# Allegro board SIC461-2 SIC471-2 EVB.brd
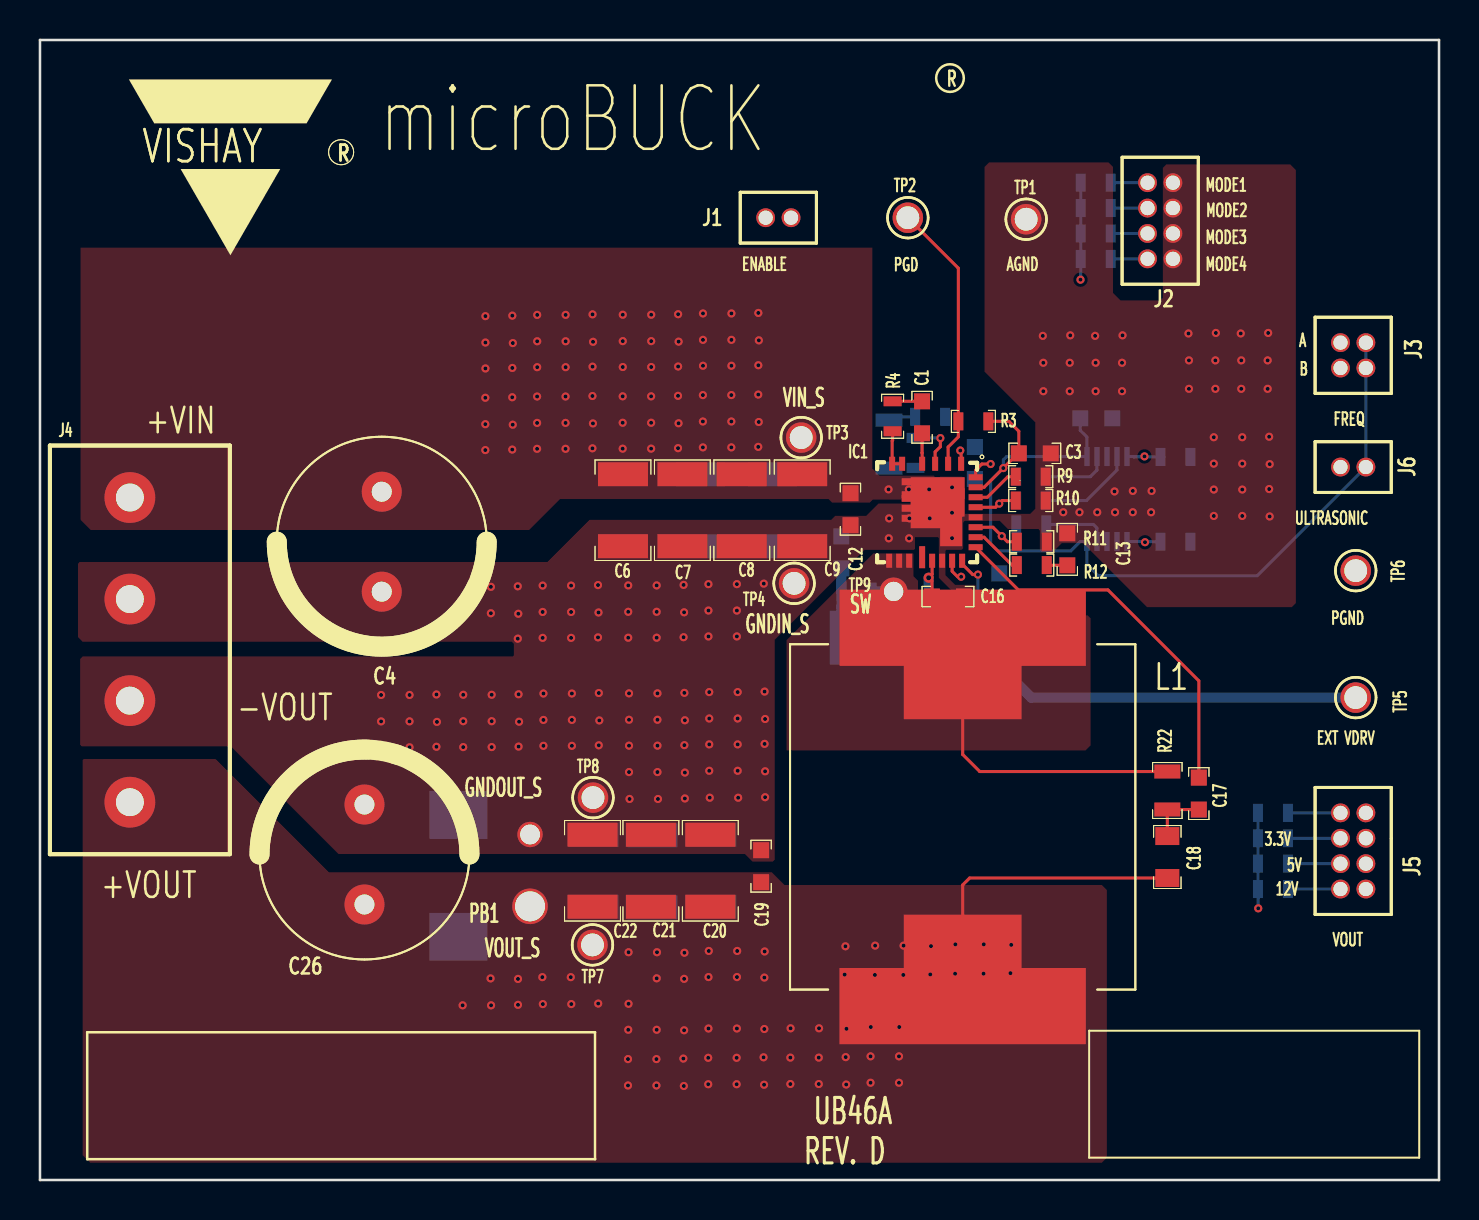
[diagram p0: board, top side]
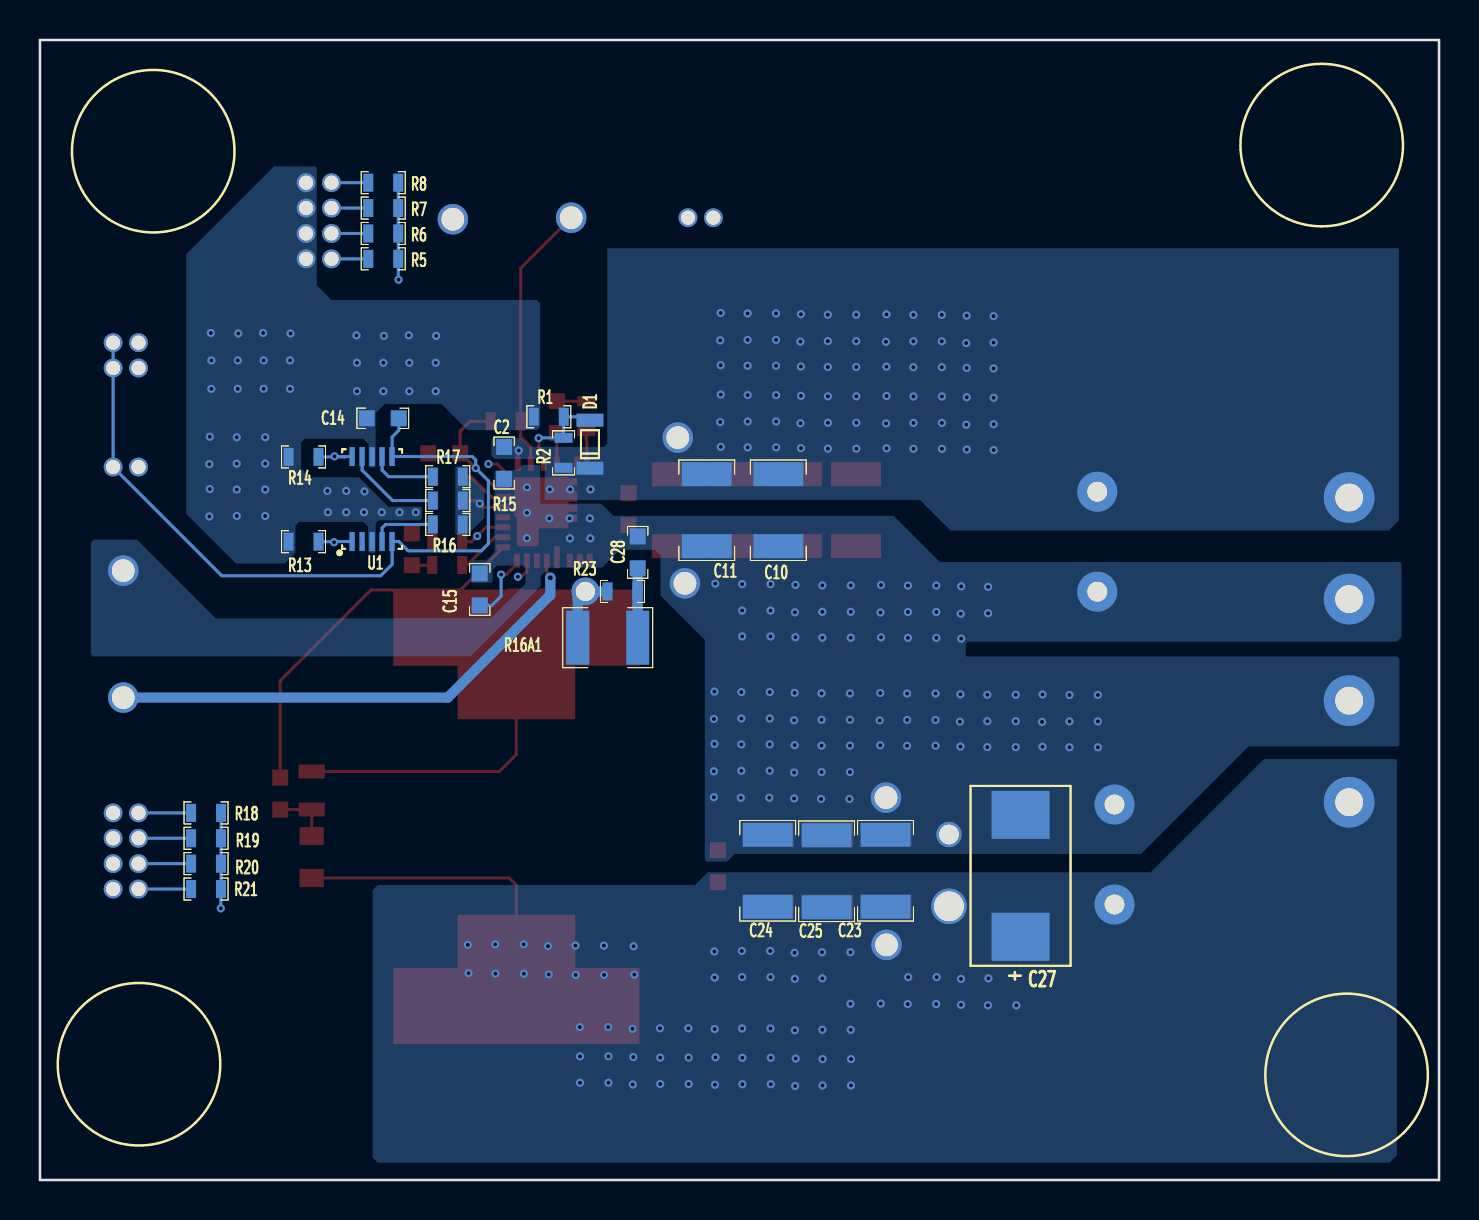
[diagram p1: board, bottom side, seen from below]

Outline 69.98 x 57.02 mm; copper layers: TOP, LAYER2, LAYER3, LAYER4, LAYER5, BOTTOM. Coordinates in mm from the lower left corner of the outline.
Outline path: 49.02,35 49.02,35 ; 0,57.02 0,0 69.98,0 69.98,57.02 0,57.02

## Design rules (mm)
constraint set DEFAULT: min track width 0.1

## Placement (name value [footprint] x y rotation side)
C1  100n  [C0603-TDK]  44.12 38.15 270 top
C2  0.1uF  [C0603-TDK]  46.76 35.86 270 bottom
C3  1u  [C0603-TDK]  49.76 36.35 0 top
C4  100uF 63V  [CAP10P5]  17.09 31.93 270 top
C6  2.2uF  [C1210-TDK]  29.16 33.5 90 top
C7  2.2uF  [C1210-TDK]  32.13 33.5 90 top
C8  2.2uF  [C1210-TDK]  35.1 33.5 90 top
C9  2.2uF  [C1210-TDK]  38.13 33.5 90 top
C10  2.2uF  [C1210-TDK]  33.05 33.5 90 bottom
C11  2.2uF  [C1210-TDK]  36.63 33.5 90 bottom
C12  0.1uF  [C0603-TDK]  40.54 33.55 270 top
C13  1n  [C0603-TDK]  51.38 31.55 90 top
C14  1uF  [C0603-TDK]  52.83 38.1 180 bottom
C15  33nF  [C0603-TDK]  47.98 29.54 270 bottom
C16  4.7uF  [C0603-TDK]  45.42 29.18 0 top
C17  2.2nF  [C0603-TDK]  57.96 19.33 270 top
C18  560p  [C0805-TDK]  56.39 16.15 270 top
C19  0.1uF  [C0603-TDK]  36.07 15.7 270 top
C20  22uF  [C1210-TDK]  33.53 15.47 270 top
C21  22uF  [C1210-TDK]  30.56 15.47 270 top
C22  22uF  [C1210-TDK]  27.64 15.47 270 top
C23  22uF  [C1210-TDK]  27.69 15.47 270 bottom
C24  22uF  [C1210-TDK]  33.58 15.47 270 bottom
C25  22uF  [C1210-TDK]  30.63 15.44 270 bottom
C26  DNP  [CAP10P5]  16.23 16.28 90 top
C27  100uF 20V  [D3L]  20.93 15.21 90 bottom
C28  DNP  [C0603-TDK]  40.08 31.39 90 bottom
D1  8.2V  [SOD323]  42.47 36.8 90 bottom
IC1  SiC46X  [SIC471]  44.37 33.4 270 top
J1  HEADER2x1  [MINIJUMPER2]  36.3 48.13 0 top
J2  HEADER 4X2  [MINIJUMPER2X4]  56.67 46.08 180 top
J3  HEADER 2X2  [MINIJUMPER2X2]  66.32 41.88 270 top
J4  CON4  [ED120-4DS2]  4.5 34.14 270 top
J5  HEADER 4X2  [MINIJUMPER2X4]  65.05 18.36 0 top
J6  JUMPER  [MINIJUMPER2]  65.05 35.66 0 top
L1  15uH  [IHLP50506767]  46.15 18.16 270 top
NOREF  -  []  9.52 46.25 0 top
PB1  CON2  [2PROBE]  24.51 13.69 135 top
R1  10K  [R0603-VISHAY]  44.53 38.18 180 bottom
R2  DNP  [R0603-VISHAY]  43.79 36.37 90 bottom
R3  102K  [R0603-VISHAY]  46.69 37.95 180 top
R4  3.3  [R0603-VISHAY]  42.65 38.2 270 top
R5  2K  [R0603-VISHAY]  52.81 46.08 0 bottom
R6  301K  [R0603-VISHAY]  52.81 47.35 0 bottom
R7  499K  [R0603-VISHAY]  52.81 48.62 0 bottom
R8  1M  [R0603-VISHAY]  52.81 49.89 0 bottom
R9  47k  [R0603-VISHAY]  49.56 35.18 180 top
R10  DNP  [R0603-VISHAY]  49.56 33.99 180 top
R11  10K  [R0603-VISHAY]  49.61 31.93 180 top
R12  56k  [R0603-VISHAY]  49.61 30.76 180 top
R13  100k  [R0603-VISHAY]  56.79 31.93 180 bottom
R14  100k  [R0603-VISHAY]  56.79 36.17 0 bottom
R15  43.2K  [R0603-VISHAY]  49.58 33.99 180 bottom
R16  64.9K  [R0603-VISHAY]  49.58 32.79 0 bottom
R16A1  DNP  [1210]  41.58 27.13 180 bottom
R17  43.2K  [R0603-VISHAY]  49.58 35.18 180 bottom
R18  DNP  [R0603-VISHAY]  61.67 18.36 180 bottom
R19  31.6K  [R0603-VISHAY]  61.67 17.09 180 bottom
R20  52.3K  [R0603-VISHAY]  61.67 15.82 180 bottom
R21  52.3K  [R0603-VISHAY]  61.67 14.55 180 bottom
R22  49.9K  [R0805-VISHAY]  56.39 19.48 90 top
R23  DNP  [R0603-VISHAY]  40.84 29.44 180 bottom
TP1  CON1  [TP30]  49.33 48.06 0 top
TP2  CON1  [TP30]  43.41 48.13 0 top
TP3  CON1  [TP30]  38.07 37.13 0 top
TP4  CON1  [TP30]  37.72 29.84 0 top
TP5  CON1  [TP30]  65.81 24.13 0 top
TP6  CON1  [TP30]  65.81 30.48 0 top
TP7  CON1  [TP30]  27.64 11.76 0 top
TP8  CON1  [TP30]  27.66 19.13 0 top
TP9  5002  [TP]  42.7 29.44 0 top
U1  DG2034  [MSOP10]  53.37 34.06 180 bottom

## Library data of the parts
C1 C3 = CAPACITOR NON-POL
C2 C6-C25 C28 = CAP NP
C4 C26 C27 = CAP POL
D1 = DIODE ZENER
IC1 = SiC462W
J1 = CON2: User Part Number: ***
J2 J5 = HEADER 4X2
J3 = HEADER 2X2
J4 = HEADER 4
J6 = JUMPER: User Part Number: ***
L1 = INDUCTOR
PB1 = CON2
R1-R3 R5-R16 R16A1 R17-R23 = RESISTOR
R4 = R
TP1-TP8 = CON1
TP9 = TP_0
U1 = DG2034M

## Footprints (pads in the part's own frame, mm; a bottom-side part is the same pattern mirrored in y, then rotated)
2PROBE
  round 1.778 hole 1.499: 1(0,0)
  round 1.27 hole 0.991: 2(2.54,-2.54)
1210
  rect 1.15x2.7 smd: 1(-1.5,0) 2(1.5,0)
C0603-TDK
  rect 0.8x0.8 smd: 1(-0.8,0) 2(0.8,0)
C0805-TDK
  rect 0.9x1.2 smd: 1(-1.05,0) 2(1.05,0)
C1210-TDK
  rect 1.2x2.5 smd: 1(-1.8,0) 2(1.8,0)
CAP10P5
  round 2 hole 1: 1(-2.5,0) 2(2.5,0)
D3L
  rect 2.4x2.9 smd: 1(-3.05,0) 2(3.05,0)
ED120-4DS2
  round 2.54 hole 1.397: 1(0,0) 2(5.08,0) 3(10.16,0) 4(15.24,0)
IHLP50506767
  custom 1.619x1.619 smd: 1(-8.128,0) 2(8.128,0)
MINIJUMPER2
  round 0.94 hole 0.711: 1(0,0) 2(1.27,0)
MINIJUMPER2X2
  round 0.94 hole 0.711: 1(0,0) 2(1.27,0) 3(0,-1.27) 4(1.27,-1.27)
MINIJUMPER2X4
  round 0.94 hole 0.711: 1(0,0) 2(1.27,0) 3(0,-1.27) 4(1.27,-1.27) 5(0,-2.54) 6(1.27,-2.54) 7(0,-3.81) 8(1.27,-3.81)
MSOP10
  rect 0.27x0.95 smd: 1(-1,-2.125) 2(-0.5,-2.125) 3(0,-2.125) 4(0.5,-2.125) 5(1,-2.125) 6(1,2.125) 7(0.5,2.125) 8(0,2.125) 9(-0.5,2.125) 10(-1,2.125)
R0603-VISHAY
  rect 0.5x0.9 smd: 1(-0.75,0) 2(0.75,0)
R0805-VISHAY
  rect 0.7x1.3 smd: 1(-0.95,0) 2(0.95,0)
SIC471
  rect 0.7x0.3 smd: 1(-2.425,1.7) 2(-2.425,1.05) 3(-2.425,0.4) 4(-2.425,-0.25) 5(-2.425,-1.25) 6(-2.425,-1.75) 12(2.425,-1.9) 13(2.425,-1.4) 14(2.425,-0.9) 16(2.425,0.25) 17(2.425,0.75) 18(2.425,1.25) 19(2.425,1.75)
  custom 0.275x0.275 smd: 7(-1.2,0.3)
  round 0 smd: 8(-0.914,-2.54) 10(0.66,-2.565) 11(1.168,-2.515)
  custom 0.5x0.5 smd: 9(-0.2,0.3)
  rect 1.1x0.3 smd: 15(2.25,-0.25)
  rect 0.3x0.7 smd: 20(1.75,2.425) 21(1.25,2.425) 22(0.75,2.425) 23(0.25,2.425) 24(-0.25,2.425) 25(-0.75,2.425) 26(-1.25,2.425) 27(-1.75,2.425)
  rect 3.4x1.1 smd: 28(0,1.2)
SOD323
  rect 0.65x1.35 smd: 1(-1.2,0) 2(1.2,0)
TP
  round 1.397 hole 0.965: 1(0,0)
TP30
  round 1.524 hole 1.143: 1(0,0)

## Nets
GND: C2.2 C3.2 C4.2 C6.1 C7.1 C8.1 C9.1 C10.1 C11.1 C12.2 C13.2 C14.1 C15.1 C16.2 C19.1 C20.1 C21.1 C22.1 C23.1 C24.1 C25.1 C26.2 C27.2 C28.2 IC1.9 IC1.10 IC1.11 IC1.17 IC1.23 IC1.28 J1.2 J2.1 J2.3 J2.5 J2.7 J4.2 J4.3 PB1.2 R1.1 R9.1 R10.1 R11.1 R13.1 R14.2 TP1.1 TP4.1 TP6.1 TP8.1 U1.3 U1.8
VDD1: C3.1 C14.2 IC1.26 J3.1 J3.2(4) J6.2 R3.1 U1.5 U1.6(V+)
VIN: C2.1 C4.1 C6.2 C7.2 C8.2 C9.2 C10.2 C11.2 C12.1 D1.1(CATHODE) IC1.1 IC1.7 IC1.8 J4.1 R2.1 TP3.1
COMP: IC1.21 R12.2
EN: D1.2 IC1.3 J1.1 R1.2 R2.2
FSW: IC1.24 R10.2 R15.2 R16.1 R17.2
GL: IC1.15
ILIM: IC1.25 R9.2
PGD: IC1.2 R3.2 TP2.1
VO: C18.2 C19.2 C20.2 C21.2 C22.2 C23.2 C24.2 C25.2 C26.1 C27.1 J4.4 L1.2 PB1.1 R18.2 R19.2 R20.2 R21.2 TP7.1
N9136645: IC1.12 IC1.13 IC1.14 L1.1 R16A1.1 R22.2 R23.1 TP9.1
N9138289: IC1.22 J5.2 J5.4 J5.6 J5.8 R11.2
N9138679: C13.1 R12.1
N9140488: C1.1 R4.1
N9140516: C1.2 IC1.4
N9145499: C16.1 IC1.16 TP5.1
N10371426: IC1.5 IC1.6 R4.2
N10441290: IC1.18 J6.1
N10450769: C17.1 IC1.20(VSNS)
N10621393: C17.2 C18.1 R22.1
N10653497: IC1.27 R5.1 R6.1 R7.1 R8.1
N10653505: J2.2 R5.2
N10653567: J2.4 R6.2
N10653613: J2.6 R7.2
N10653671: J2.8 R8.2
N16777491: J5.1 R18.1
N16777524: J5.3 R19.1
N16777532: J5.5 R20.1
N16777536: J5.7 R21.1
N16796780: C28.1 R16A1.2 R23.2
N16799725: J3.3 R13.2 U1.1
N16799736: J3.4 R14.1 U1.10
N16799803: R15.1 U1.9
N16799837: R16.2 U1.4
N16799839: R17.1 U1.7
N1041946515: C15.2 IC1.19

Pads without a net: U1 2

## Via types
v1: diameter 0.406, hole 0.203, TOP to BOTTOM, 290 vias
v2: diameter 0.508, hole 0.254, TOP to BOTTOM, 1 via

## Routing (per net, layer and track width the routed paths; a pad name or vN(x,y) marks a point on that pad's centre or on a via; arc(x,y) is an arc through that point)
GND:
  vias: v1(17.06,24.26) v1(17.06,22.94) v1(17.06,21.64) v1(18.48,24.26) v1(18.48,22.94) v1(18.48,21.64) v1(19.83,24.29) v1(19.86,22.91) v1(19.83,21.67) v1(21.17,24.27) v1(21.17,22.95) v1(21.17,21.65) v1(22.55,29.67) v1(22.55,28.35) v1(22.59,24.27) v1(22.59,22.95) v1(22.59,21.65) v1(23.9,29.7) v1(23.92,28.32) v1(23.9,27.08) v1(23.94,24.3) v1(23.96,22.92) v1(23.94,21.68) v1(25.14,29.73) v1(25.14,28.41) v1(25.14,27.12) v1(25.18,24.33) v1(25.18,23.01) v1(25.18,21.72) v1(26.57,29.73) v1(26.57,28.41) v1(26.57,27.12) v1(26.6,24.33) v1(26.6,23.01) v1(26.6,21.72) v1(27.91,29.76) v1(27.94,28.39) v1(27.91,27.14) v1(27.95,24.36) v1(27.95,21.74) v1(27.98,22.99) v1(29.42,29.74) v1(29.42,28.42) v1(29.42,27.13) v1(29.46,24.34) v1(29.46,23.02) v1(29.46,21.73) v1(29.46,20.41) v1(29.49,19.06) v1(30.85,29.74) v1(30.85,28.42) v1(30.85,27.13) v1(30.88,24.34) v1(30.88,23.02) v1(30.88,21.73) v1(30.88,20.41) v1(30.91,19.06) v1(32.19,29.77) v1(32.22,28.4) v1(32.19,27.15) v1(32.23,24.37) v1(32.26,23) v1(32.23,21.75) v1(32.26,20.38) v1(32.26,19.08) v1(33.44,29.81) v1(33.44,28.48) v1(33.44,27.19) v1(33.47,24.41) v1(33.47,23.08) v1(33.47,21.79) v1(33.47,20.47) v1(33.5,19.12) v1(34.86,29.81) v1(34.86,28.48) v1(34.86,27.19) v1(34.9,24.41) v1(34.9,23.08) v1(34.9,21.79) v1(34.9,20.47) v1(34.92,19.12) v1(36.2,29.83) v1(36.24,24.43) v1(36.27,23.06) v1(36.24,21.81) v1(36.27,20.44) v1(36.27,19.15) v1(42.47,33.1) v1(42.45,32.1) v1(43.47,32.1) v1(43.49,33.1) v1(44.5,33.1) v1(45.62,34.65) v1(45.62,33.38) v1(45.62,32.11) v1(50.16,42.22) v1(50.18,40.88) v1(50.18,39.46) v1(51.18,33.4) v1(51.53,42.25) v1(51.51,40.88) v1(51.51,39.46) v1(51.99,33.4) v1(52.78,42.22) v1(52.8,40.88) v1(52.8,39.46) v1(52.88,33.4) v1(53.75,34.44) v1(53.77,33.4) v1(54.15,42.25) v1(54.12,40.88) v1(54.12,39.46) v1(54.66,34.47) v1(54.66,33.4) v1(55.58,33.4) v1(55.6,34.47) v1(57.44,42.34) v1(57.47,41) v1(57.47,39.57) v1(58.71,37.15) v1(58.71,35.83) v1(58.71,34.54) v1(58.71,33.22) v1(58.82,42.37) v1(58.79,41) v1(58.79,39.57) v1(60.06,42.34) v1(60.09,41) v1(60.09,39.57) v1(60.13,37.15) v1(60.13,35.83) v1(60.13,34.54) v1(60.13,33.22) v1(61.43,42.37) v1(61.41,41) v1(61.41,39.57) v1(61.48,37.18) v1(61.51,35.81) v1(61.48,34.56) v1(61.51,33.19)
VDD1: length 45.4
  TOP w0.152: IC1.26 47.22,34.65 v1(48.18,35.61) 48.92,36.35 C3.1 48.96,37.45 48.46,37.95 R3.1
  BOTTOM w0.152: C14.2 52.03,37.5 52.37,37.16 U1.6 48.35,36.19 48.18,36.02 v1(48.18,35.61) 47.55,34.98 47.55,31.83 47.9,31.47 51.56,31.47 52.03,31.94 U1.5 52.37,30.79 52.93,30.23 60.88,30.23 J6.2 J3.2 J3.1
VIN: length 0.7
  TOP w0.152: v1(46.03,36.49) 46.07,36.45 IC1.1
  vias: v1(22.27,39.13) v1(22.27,37.81) v1(22.27,36.51) v1(22.28,43.21) v1(22.28,41.89) v1(22.28,40.59) v1(23.63,43.24) v1(23.65,41.86) v1(23.63,40.62) v1(23.62,39.15) v1(23.65,37.78) v1(23.62,36.54) v1(24.87,43.27) v1(24.87,41.95) v1(24.87,40.66) v1(24.86,39.19) v1(24.86,37.87) v1(24.86,36.57) v1(26.29,43.27) v1(26.29,41.95) v1(26.29,40.66) v1(26.29,39.19) v1(26.29,37.87) v1(26.29,36.57) v1(27.64,43.3) v1(27.66,41.93) v1(27.64,40.68) v1(27.63,39.22) v1(27.66,37.84) v1(27.63,36.6) v1(29.15,43.28) v1(29.15,41.96) v1(29.15,40.67) v1(29.14,39.2) v1(29.14,37.88) v1(29.14,36.58) v1(30.57,43.28) v1(30.57,41.96) v1(30.57,40.67) v1(30.57,39.2) v1(30.57,37.88) v1(30.57,36.58) v1(31.92,43.31) v1(31.94,41.94) v1(31.92,40.69) v1(31.91,39.22) v1(31.94,37.85) v1(31.91,36.61) v1(33.16,43.34) v1(33.16,42.02) v1(33.16,40.73) v1(33.16,39.26) v1(33.16,37.94) v1(33.16,36.65) v1(34.58,43.34) v1(34.58,42.02) v1(34.58,40.73) v1(34.58,39.26) v1(34.58,37.94) v1(34.58,36.65) v1(35.93,43.37) v1(35.96,42) v1(35.93,40.75) v1(35.93,39.29) v1(35.95,37.92) v1(35.93,36.67) v1(42.44,34.54) v1(43.46,34.54) v1(44.48,34.54)
COMP: length 2.6
  TOP w0.152: R12.2 48.62,30.76 47.22,32.15 IC1.21
EN: length 25.4
  TOP w0.152: IC1.3 44.77,36.42 45.03,36.68 v1(45.03,37.11)
  LAYER3 w0.152: J1.1 36.3,49.3 36.6,49.6 41.23,49.6 42.06,48.77 42.06,40.08 v1(45.03,37.11)
  BOTTOM w0.152: v1(45.03,37.11) 45.03,37.12 R2.2 43.79,38.16 R1.2 42.64,38.18 D1.2
FSW: length 2.2
  TOP w0.152: IC1.24 47.8,33.65 v1(47.98,33.83) 48.13,33.99 R10.2
  BOTTOM w0.152: 48.83,32.74 R16.1
ILIM: length 2.4
  TOP w0.152: IC1.25 47.38,34.15 48.41,35.18 R9.2
PGD: length 13.6
  TOP w0.152: TP2.1 45.94,45.61 R3.2 45.94,37.17 45.42,36.66 IC1.2
VO: length 56.8
  TOP w0.152: 46.15,10.03 46.15,14.76 46.5,15.1 C18.2
  LAYER3 w0.152: TP7.1 31.09,8.31 55.65,8.31 v1(60.93,13.59)
  BOTTOM w0.152: R18.2 R19.2 R20.2 R21.2 60.93,14.54 v1(60.93,13.59)
  vias: v1(21.14,8.74) v1(22.54,10.08) v1(22.56,8.74) v1(23.91,10.06) v1(23.91,8.76) v1(25.13,10.15) v1(25.15,8.8) v1(26.55,10.15) v1(26.57,8.8) v1(27.92,8.83) v1(29.44,11.39) v1(29.44,8.81) v1(29.42,7.52) v1(29.41,6.05) v1(29.41,4.73) v1(30.86,11.39) v1(30.85,10.09) v1(30.85,7.52) v1(30.83,6.05) v1(30.83,4.73) v1(32.23,11.37) v1(32.22,10.06) v1(32.22,7.49) v1(32.18,6.07) v1(32.21,4.7) v1(33.45,11.46) v1(33.44,10.15) v1(33.44,7.58) v1(33.42,6.11) v1(33.42,4.79) v1(34.87,11.46) v1(34.86,10.15) v1(34.86,7.58) v1(34.85,6.11) v1(34.85,4.79) v1(36.25,11.43) v1(36.23,10.13) v1(36.23,7.55) v1(36.19,6.14) v1(36.22,4.77) v1(37.54,7.59) v1(37.53,6.12) v1(37.53,4.8) v1(38.97,7.59) v1(38.95,6.12) v1(38.95,4.8) v1(40.25,10.28) v1(40.29,11.69) v1(40.34,7.56) v1(40.3,6.15) v1(40.33,4.78) v1(41.56,7.65) v1(41.54,6.19) v1(41.54,4.86) v1(41.77,11.72) v1(41.76,10.26) v1(42.97,6.19) v1(42.97,4.86) v1(42.98,7.65) v1(43.2,11.72) v1(43.18,10.26) v1(44.57,11.7) v1(44.53,10.28) v1(45.77,10.32) v1(45.78,11.79) v1(47.21,11.79) v1(47.19,10.32) v1(48.54,10.35) v1(48.58,11.76)
N9136645: length 19.2
  TOP w0.152: L1.1 46.15,21.29 47.01,20.43 R22.2
  BOTTOM w0.508: R23.1 TP9.1 43.08,29.06 R16A1.1
N9138289: length 30.9
  TOP w0.152: IC1.22 47.66,32.65 v1(48.11,32.21) 48.39,31.93 R11.2
  LAYER3 w0.152: J5.8 J5.6 J5.4 J5.2 66.32,19.68 53.8,32.21 v1(48.11,32.21)
N9138679: length 1
  TOP w0.152: C13.1 50.37,30.75 R12.1
N9140488: length 1.5
  TOP w0.152: 42.66,38.95 R4.1 ; 42.66,38.95 C1.1 ; 42.66,38.95 42.65,38.94
N9140516: length 1.5
  TOP w0.152: IC1.4 44.12,36.38 44.12,36.38 C1.2
N9145499: length 26.3
  TOP w0.152: C16.1 44.62,29.96 v2(44.45,30.12) 44.62,30.3 IC1.16
  BOTTOM w0.508: v2(44.45,30.12) 44.45,29.26 49.58,24.13 TP5.1
N10371426: length 2.1
  TOP w0.152: R4.2 42.65,37 42.62,36.98 IC1.6 IC1.5
N10441290: length 24
  TOP w0.152: IC1.18 45.62,30.45 45.9,30.18 v1(46.08,30.18)
  LAYER3 w0.152: J6.1 65.05,33.83 63.88,32.66 47.57,32.66 46.08,31.17 v1(46.08,30.18)
N10450769: length 18.8
  TOP w0.152: C17.1 57.96,24.97 53.42,29.51 48.93,29.51 IC1.20
N10621393: length 2.9
  TOP w0.152: C18.1 R22.1 57.5,18.53 57.51,18.53 C17.2
N10653497: length 17.2
  TOP w0.152: IC1.27 46.8,35.5 47.11,35.81 v1(47.55,35.81)
  LAYER3 w0.152: v1(52.04,45.03) 47.55,40.54 v1(47.55,35.81) 47.52,35.79
  BOTTOM w0.152: R8.1 R7.1 R6.1 R5.1 52.06,45.05 v1(52.04,45.03)
N10653505: length 1.8
  BOTTOM w0.152: J2.2 R5.2
N10653567: length 1.8
  BOTTOM w0.152: J2.4 R6.2
N10653613: length 1.8
  BOTTOM w0.152: J2.6 R7.2
N10653671: length 1.8
  BOTTOM w0.152: J2.8 R8.2
N16777491: length 2.6
  BOTTOM w0.152: J5.1 R18.1
N16777524: length 2.6
  BOTTOM w0.152: J5.3 R19.1
N16777532: length 2.6
  BOTTOM w0.152: J5.5 R20.1
N16777536: length 2.6
  BOTTOM w0.152: J5.7 R21.1
N16796780: length 3.5
  BOTTOM w0.508: C28.1 40.08,29.45 R23.2 40.09,28.69 40.08,28.68 R16A1.2
N16799725: length 28.5
  LAYER3 w0.152: J3.3 65.05,42.8 65.35,43.1 67.79,43.1 68.07,42.82 68.07,33.96 66.01,31.9 v1(55.27,31.9)
  BOTTOM w0.152: U1.1 55.24,31.94 55.24,31.93 ; 55.24,31.93 55.22,31.9 ; 55.24,31.93 R13.2 ; 55.24,31.93 v1(55.27,31.9)
N16799736: length 14
  LAYER3 w0.152: J3.4 62.89,38.46 57.51,38.46 v1(55.24,36.2)
  BOTTOM w0.152: 54.7,36.19 55.24,36.19 v1(55.24,36.2) ; 54.7,36.19 U1.10 ; 54.7,36.19 54.72,36.17 R14.1 56.22,36.17
N16799803: length 4.8
  BOTTOM w0.152: R15.1 52.34,33.99 53.87,35.51 U1.9
N16799837: length 3.3
  BOTTOM w0.152: R16.2 52.69,32.79 52.87,32.61 U1.4
N16799839: length 3.3
  BOTTOM w0.152: R17.1 52.54,35.18 52.87,35.51 U1.7
N1041946515: length 3.5
  TOP w0.152: IC1.19 46.12,30.81 46.65,30.28 v1(46.91,30.28)
  BOTTOM w0.152: v1(46.91,30.28) 46.91,29.2 47.38,28.74 C15.2

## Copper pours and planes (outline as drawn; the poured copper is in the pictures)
GND on TOP: outline of 85 points within 1.91,15.93 62.81,50.9
GND on BOTTOM: 41.3,33.22 41.91,33.83 44.93,33.83 44.96,33.86 44.96,35.74 44.98,35.76 45.85,35.76 46.1,35.51 47.17,35.51 47.24,35.43 47.24,31.39 47.65,30.99 48.31,30.99 48.44,30.86 48.44,29.92 48.39,29.87 47.42,29.87 47.34,29.95 47.34,30.5 47.12,30.73 45.74,30.73 45.69,30.68 45.69,29.82 47.42,28.09 61.19,28.09 65.12,32.03 67.28,32.03 67.44,31.88 67.44,26.29 67.33,26.19 48.46,26.19 44.93,29.72 44.93,30.23 44.53,30.63 41.86,30.63 40.97,31.52 39.22,31.52 38.94,31.24 38.94,29.23 36.73,27.03 36.73,16.03 36.63,15.93 35.61,15.93 35.23,16.31 14.91,16.31 9.55,21.67 9.55,21.69 2.06,21.69 1.98,21.77 1.98,26.06 2.11,26.19 23.62,26.19 23.67,26.24 23.67,26.82 23.57,26.92 2.11,26.92 1.88,27.15 1.88,30.84 1.95,30.91 24.97,30.91 27.28,33.22
GND on BOTTOM: 53.49,31.37 53.57,31.45 53.57,32.69 53.8,32.92 57.02,32.92 57.2,32.74 57.2,31.37 57.73,30.84 60.17,30.84 62.66,33.32 62.66,46.3 58.27,50.7 56.18,50.7 56.13,50.65 56.13,44.75 55.4,44.02 45.14,44.02 44.96,43.84 44.96,37.67 45.11,37.52 48.59,37.52 49.89,38.81 52.73,38.81 53.19,38.35 53.19,35.69 53.24,35.64 53.49,35.64 53.54,35.69 53.54,36.8 53.82,37.08 56.72,37.08 56.92,36.88 56.92,35.61 56.46,35.15 54.03,35.15 52.55,33.68 50.93,33.68 50.88,33.63 50.88,33.1 50.98,32.99 53.06,32.99 53.19,32.87 53.19,31.42 53.24,31.37
GND on LAYER2: 1.06,55.87 1.06,0.8 55.47,0.8 55.52,0.86 55.52,27.17 55.44,27.25 46.35,27.25 45,28.59 45,35.3 44.49,35.81 42.59,35.81 33.29,45.1 33.29,55.8 33.22,55.87
GND on LAYER2: 69.03,0.93 69.03,55.87 33.8,55.87 33.7,55.77 33.7,45.03 42.54,36.19 44.62,36.19 45.26,35.55 45.26,28.82 46.68,27.4 55.44,27.4 55.7,27.14 55.7,0.88 55.77,0.8 68.9,0.8
GND on LAYER3: 44.98,35.13 45.03,35.18 48.06,35.18 48.72,35.84 48.72,38.96 47.24,40.44 47.24,50.67 47.47,50.9 53.44,50.9 53.67,50.67 53.67,44.37 54.05,43.99 56.03,43.99 56.16,44.12 56.16,50.62 56.34,50.8 62.53,50.8 62.81,50.52 62.81,33.55 62.79,33.55 62.13,32.89 46.96,32.89 45.59,31.52 42.27,31.52 41.4,30.66 41.4,28.68 43.23,26.85 58.22,26.85 59.51,25.55 59.51,16.43 59.39,16.31 14.94,16.31 9.58,21.67 9.58,21.69 2.08,21.69 2.01,21.77 2.01,26.06 2.13,26.19 23.65,26.19 23.7,26.24 23.7,26.82 23.6,26.92 2.13,26.92 1.91,27.15 1.91,31.42 1.96,31.47 24.41,31.47 26.62,33.68 44.91,33.68 44.98,33.76
GND on LAYER4: 1.07,55.88 1.07,0.81 55.47,0.81 55.52,0.86 55.52,27.18 55.45,27.25 46.35,27.25 45.01,28.6 45.01,35.31 44.5,35.81 42.6,35.81 33.3,45.11 33.3,55.8 33.22,55.88
GND on LAYER4: 69.04,0.94 69.04,55.88 33.81,55.88 33.71,55.78 33.71,45.03 42.54,36.2 44.63,36.2 45.26,35.56 45.26,28.83 46.69,27.41 55.45,27.41 55.7,27.15 55.7,0.89 55.78,0.81 68.91,0.81
GND on LAYER5: 61.98,27.43 61.98,51.13 61.82,51.28 45.49,51.28 45.21,51 45.21,29.44 47.22,27.43
GND on LAYER5: 41.33,33.22 41.94,33.83 44.96,33.83 44.96,29.01 46.71,27.25 52.88,27.25 53.57,26.57 53.57,15.47 53.24,15.14 37.87,15.14 37.74,15.27 37.74,15.32 36.75,16.31 14.94,16.31 9.58,21.67 9.58,21.69 2.08,21.69 2.01,21.77 2.01,26.06 2.13,26.19 23.65,26.19 23.7,26.24 23.7,26.82 23.6,26.92 2.13,26.92 1.91,27.15 1.91,30.84 1.98,30.91 24.99,30.91 27.3,33.22
VIN on TOP: 39.62,33.88 41.5,33.88 41.66,34.04 44.73,34.04 44.75,34.06 44.75,35.18 44.7,35.23 41.99,35.23 41.63,35.59 41.63,46.63 2.03,46.63 2.03,33.02 2.54,32.51 24.46,32.51 26.01,34.06 39.45,34.06
VIN on BOTTOM: 44.7,34.01 44.73,34.04 44.73,35.99 44.8,36.07 47.24,36.07 47.4,36.22 47.4,37.08 47.37,37.11 45.95,37.11 45.52,36.68 41.76,36.68 41.6,36.83 41.6,46.61 2.01,46.61 2.01,32.99 2.51,32.49 24.43,32.49 25.96,34.01
VIN on LAYER3: 44.73,34.01 44.75,34.04 44.75,36.2 41.63,39.32 41.63,46.61 2.03,46.61 2.03,32.99 2.54,32.49 24.46,32.49 25.98,34.01
VIN on LAYER5: 44.73,34.01 44.75,34.04 44.75,36.68 44.35,37.08 44.35,46.53 44.07,46.81 2.24,46.81 2.03,46.61 2.03,32.99 2.54,32.49 24.46,32.49 25.98,34.01
FSW on BOTTOM: 48.62,35.69 49.15,35.69 49.2,35.64 49.2,32.33 49.12,32.26 48.62,32.26 47.75,33.12 47.75,34.49 48.56,35.31 48.56,35.64
VO on TOP, LAYER5: 37.24,14.76 36.6,15.39 14.45,15.39 8.79,21.06 2.18,21.06 2.13,21.01 2.13,1.24 2.51,0.86 53.11,0.86 53.37,1.12 53.37,14.5 53.11,14.76
VO on BOTTOM: 37.21,14.76 36.58,15.39 14.43,15.39 8.76,21.06 2.16,21.06 2.11,21.01 2.11,1.24 2.49,0.86 53.09,0.86 53.34,1.12 53.34,14.5 53.09,14.76
VO on LAYER3: 2.51,0.86 2.13,1.24 2.13,21.01 2.18,21.06 8.79,21.06 14.45,15.39 36.6,15.39 37.24,14.76 53.11,14.76 53.37,14.5 53.37,8.61 31.5,8.61 28.47,11.63 28.47,12.27 28.19,12.55 27.03,12.55 26.85,12.37 26.85,10.87 26.97,10.74 28.35,10.74 31.04,8.05 53.37,8.05 53.37,1.12 53.11,0.86
N9136645 on TOP: 41.68,31.34 43.66,31.34 43.69,31.32 43.69,30.2 43.92,29.97 43.92,28.5 44.17,28.24 52.4,28.24 52.55,28.09 52.55,21.74 52.3,21.49 37.34,21.49 37.34,27

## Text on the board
Ref Des/Silkscreen Top: ENABLE | PGD | AGND | MODE1 | MODE3 | MODE4 | MODE2 | 3.3V | 12V | 5V | ULTRASONIC | A | B | EXT VDRV | PGND | VOUT | FREQ | R | GNDOUT_S | PB1 | VOUT_S | GNDIN_S | VIN_S | SW | REV. D | UB46A | +VOUT | +VIN | -VOUT | microBUCK
FAB: Layer3 | Layer2 | Bottom | Layer4 | Layer5 | Top | TOTAL THICKNESS - 0.062 -.008/+.005 | 2OZ | 1 THIS IS A 6 LAYER BOARD WITH COMPONENTS ON BOTH SIDES. | 3 SILKSCREEN BOTH SIDES WITH WHITE NON CONDUCTIVE EPOXY BASED INK | 4 IMMERSION GOLD FINISH | 2 SMT LAND PATTERNS THAT HAVE A FINISHED PAD WIDTH RANGING FROM | 6 Material Type: IT175A | 5 GREEN SOLDER MASK | .012 TO .015 MUST USE THE FOLLOWING TOLERANCE, +.002-.0005. | PB VENDOR TO ADJUST ARTWORK TO COMPENSATE FOR ETCH PROCESS. | NOTES: UNLESS OTHERWISE SPECIFIED:
